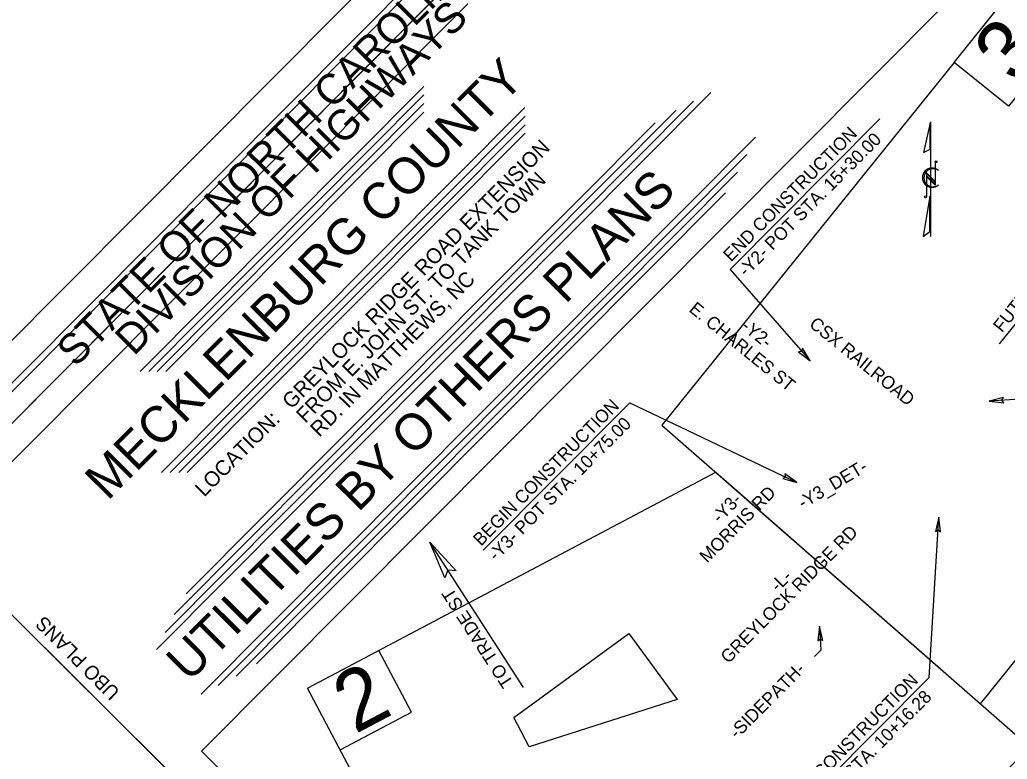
# Model space of a CAD drawing. Extents: x 1484850 to 1495577, y 495475 to 506245.
# Drawn here: x 1486494 to 1488945, y 498431 to 500266 of the extents above; entities that cross this region are included whole.
import ezdxf

# ---------------------------------------------------------------- set-up
doc = ezdxf.new("R2010")
doc.units = 0
for name, color, linetype in [('Cell Prop Down Guy _B', 7, 'Continuous'), ('Exist Conduit _B', 7, 'Continuous'), ('Exist Utilities Sanitary Sewer Manhole CELL', 7, 'Continuous'), ('Exist Utilities Telephone UG Cable SUE LOS C', 7, 'Continuous'), ('Exist Utilities Telephone UG FO SUE LOS C', 7, 'Continuous'), ('Exist Utilities Water Fire Hydrant CELL', 7, 'Continuous'), ('Exist Utilities Water Meter CELL', 7, 'Continuous'), ('Exist Utilities Water UG Line SUE LOS B', 7, 'Continuous'), ('Exist Utilities Water UG Line SUE LOS C', 7, 'Continuous'), ('Exist Utilities Water Valve CELL', 7, 'Continuous'), ('P Pole (Pow Co) CELL', 7, 'Continuous'), ('Prop Conduit _B', 7, 'Continuous'), ('Prop Guy Wire', 7, 'Continuous'), ('Prop OH Pow Lines', 7, 'Continuous'), ('Prop UG Pow Cables', 7, 'Continuous')]:
    doc.layers.add(name, color=color, linetype=linetype)

msp = doc.modelspace()

# ---------------------------------------------------------------- linework, layer by layer
at = {"layer": 'Cell Prop Down Guy _B'}
msp.add_line((1485019.4, 497803.9), (1488584.2, 501383.6), dxfattribs=at)
msp.add_lwpolyline([(1485019.4, 497803.9), (1488584.2, 501383.6), (1490922.5, 499055), (1487357.7, 495475.3)], close=True, dxfattribs=at)
at = {"layer": 'Exist Utilities Sanitary Sewer Manhole CELL'}
for points in [[(1488427.6, 499442.4), (1488455.9, 499419.4), (1488436.9, 499450.9), (1488435.1, 499443.2)], [(1488936.2, 499328.4), (1488900.6, 499320), (1488937.2, 499315.8), (1488932.2, 499321.9)], [(1488388, 499127.6), (1488423.2, 499117.7), (1488393.3, 499139.1), (1488394.7, 499131.3)], [(1488779.9, 498995.6), (1488775.9, 499031.9), (1488767.3, 498996.2), (1488773.9, 499000.4)], [(1487549.6, 498881.6), (1487511.9, 498969.7), (1487577.7, 498899.1), (1487557, 498900.1)], [(1488487.6, 498726.2), (1488479.7, 498761.9), (1488475.1, 498725.4), (1488481.2, 498730.3)]]:
    msp.add_lwpolyline(points, close=True, dxfattribs=at)
at = {"layer": 'Exist Utilities Telephone UG Cable SUE LOS C'}
for points in [[(1486945.7, 498451.8), (1488980.9, 500495.4), (1490008.1, 499472.4), (1487973, 497428.8)], [(1486945.7, 498451.8), (1488980.9, 500495.4), (1490008.1, 499472.4), (1487973, 497428.8)], [(1487759, 498462.3), (1487720.6, 498534.8), (1488006.4, 498743.3), (1488126.2, 498579.3)]]:
    msp.add_lwpolyline(points, close=True, dxfattribs=at)
at = {"layer": 'Exist Utilities Telephone UG FO SUE LOS C'}
for points in [[(1488813.3, 500160.1), (1488938.9, 500315.8), (1489073.9, 500206.9)], [(1487289.7, 498454.6), (1487466.6, 498548.1), (1487385.6, 498701.5)]]:
    msp.add_lwpolyline(points, dxfattribs=at)
for points in [[(1488948.4, 500051.2), (1488813.3, 500160.1), (1488087.8, 499260.5), (1488879.1, 498569.1), (1489756.2, 499656.7), (1489073.9, 500206.9)], [(1487208.7, 498608.1), (1488222.1, 499143.2), (1488965.4, 498493.7), (1489025.4, 498380), (1487698.9, 497679.6)]]:
    msp.add_lwpolyline(points, close=True, dxfattribs=at)
at = {"layer": 'Exist Utilities Water Fire Hydrant CELL'}
for p, q in [((1488755.5, 499728.3), (1488755.8, 500012.8)), ((1488766.4, 499913.8), (1488766.4, 499855.4)), ((1488766.4, 499864.5), (1488744.6, 499886.3)), ((1488744.6, 499886.3), (1488744.6, 499826.9)), ((1488766.4, 499862.4), (1488744.6, 499884.1)), ((1488744.6, 499884.1), (1488744.6, 499878.8)), ((1488766.4, 499857), (1488744.6, 499878.8)), ((1488744.6, 499878.8), (1488766.4, 499857)), ((1488766.4, 499855.4), (1488744.6, 499877.2)), ((1488774.4, 499892), (1488774.7, 499891.8)), ((1488766.4, 499857), (1488766.4, 499862.4))]:
    msp.add_line(p, q, dxfattribs=at)
for points in [[(1488753.8, 500010.3), (1488737.5, 499936.4), (1488753.7, 499944.6)], [(1488753.3, 499828.5), (1488737.1, 499728.3), (1488753.2, 499741)]]:
    msp.add_lwpolyline(points, close=True, dxfattribs=at)
for centre in [(1488768.7, 499913.7), (1488742.3, 499826.8)]:
    msp.add_circle(centre, 2.32, dxfattribs=at)
for centre, radius, start, end in [((1488758.7, 499874.1), 23.9, 47.7961, 312.3501), ((1488761, 499874.1), 22.4, 53.0511, 308.5848)]:
    msp.add_arc(centre, radius, start, end, dxfattribs=at)
at = {"layer": 'Exist Utilities Water Meter CELL'}
for p, q in [((1488926.4, 499461.8), (1489269, 499886.6)), ((1487745, 498609.8), (1487511.9, 498969.7))]:
    msp.add_line(p, q, dxfattribs=at)
at = {"layer": 'Exist Utilities Water UG Line SUE LOS B'}
for p, q in [((1488629.3, 500020.1), (1488257.4, 499646.7)), ((1488257.4, 499646.7), (1488455.9, 499419.4)), ((1489242.3, 499341.4), (1488900.6, 499320)), ((1488009, 499315.3), (1487644.9, 498949.7)), ((1488009, 499315.3), (1488423.2, 499117.7)), ((1488751.5, 498634.5), (1488775.9, 499031.9)), ((1488479.7, 498761.9), (1488482.6, 498702.3)), ((1488482.6, 498702.3), (1488466.7, 498686.4)), ((1488751.5, 498634.5), (1488387.4, 498268.8))]:
    msp.add_line(p, q, dxfattribs=at)
at = {"layer": 'Exist Utilities Water UG Line SUE LOS C'}
for points in [[(1486441.9, 498821.9), (1486895.2, 498370.5), (1486217.1, 497689.6), (1485587.2, 498316.9), (1486082.4, 498814.2), (1486259, 498638.3)], [(1486441.9, 498821.9), (1486895.4, 498370.4), (1486217.3, 497689.5), (1485587.4, 498316.8), (1486082.5, 498814.1), (1486259, 498638.3)]]:
    msp.add_lwpolyline(points, close=True, dxfattribs=at)
at = {"layer": 'P Pole (Pow Co) CELL'}
msp.add_lwpolyline([(1488481.3, 501486.1), (1484916.4, 497906.4), (1487254.7, 495577.9), (1490819.6, 499157.6)], close=True, dxfattribs=at)
at = {"layer": 'Prop Guy Wire'}
msp.add_lwpolyline([(1487337.5, 495550.5), (1490865.3, 499093), (1488622.4, 501326.5), (1485094.6, 497784)], close=True, dxfattribs=at)
at = {"layer": 'Prop OH Pow Lines'}
for p, q in [((1487638.7, 499770.2), (1487638.7, 499770.2)), ((1487269, 499630.1), (1487269, 499630.1))]:
    msp.add_line(p, q, dxfattribs=at)
at = {"layer": 'Prop UG Pow Cables'}
for p, q in [((1486793.1, 499393.2), (1487497.5, 500100.5)), ((1486814.3, 499393.3), (1487497.5, 500079.3)), ((1486833.6, 498703.5), (1488209.3, 500085.1)), ((1486835.5, 499393.3), (1487497.6, 500058.1)), ((1486846.5, 499142.5), (1487748.3, 500048)), ((1486854.9, 498746.2), (1488166.8, 500063.6)), ((1486856.7, 499393.3), (1487497.6, 500036.9)), ((1486867.7, 499142.5), (1487748.4, 500026.8)), ((1486877.7, 498790.4), (1488122.8, 500040.6)), ((1486889, 499142.5), (1487748.4, 500005.6)), ((1486907.7, 498841.7), (1488071.5, 500010.4)), ((1486910.2, 499142.6), (1487748.5, 499984.4)), ((1486944.4, 498593.2), (1488320.2, 499974.6)), ((1486987, 498614.6), (1488299, 499932)), ((1487031.1, 498637.6), (1488276.1, 499887.9)), ((1487082.3, 498667.9), (1488246.1, 499836.5))]:
    msp.add_line(p, q, dxfattribs=at)
for points in [[(1488477.3, 501375.9), (1485344.2, 498229.8)], [(1488477.3, 501354.6), (1485471.3, 498336.1)]]:
    msp.add_lwpolyline(points, dxfattribs=at)
for points in [[(1486895.2, 498370.5), (1486217.1, 497689.6), (1485587.2, 498316.9), (1486265.2, 498997.8)], [(1485587.2, 498316.9), (1486082.4, 498814.2), (1486259, 498638.3), (1486441.9, 498821.9), (1486895, 498370.6), (1486217, 497689.7)]]:
    msp.add_lwpolyline(points, close=True, dxfattribs=at)

# ---------------------------------------------------------------- texts
at = {"layer": 'Exist Conduit _B'}
for s, height, p in [('MECKLENBURG COUNTY', 90, (1486712.2, 499070.9)), ('GREYLOCK RIDGE ROAD EXTENSION', 37.5, (1487168.4, 499298.1)), ('UTILITIES BY OTHERS PLANS', 90, (1486914.2, 498620.5)), ('FROM E. JOHN ST. TO TANK TOWN ', 37.5, (1487203.3, 499263.4)), ('RD. IN MATTHEWS, NC', 37.5, (1487238.1, 499228.7))]:
    msp.add_text(s, height=height, rotation=45.1191, dxfattribs=at).set_placement(p)
at = {"layer": 'Exist Utilities Water Meter CELL'}
for s, height, rotation, p in [('3', 150, 51.1156, (1488968.4, 500102.7)), ('END CONSTRUCTION', 32, 45.1191, (1488259.9, 499663.9)), ('-Y2- POT STA. 15+30.00', 32, 45.1191, (1488297.3, 499626.7)), ('FUTURE EXTENSION', 32, 51.1158, (1488932.5, 499488.1)), ('BEGIN CONSTRUCTION', 32, 45.1191, (1487638.9, 498958.4)), ('-Y3- POT STA. 10+75.00', 32, 45.1191, (1487676.3, 498921.1)), ('TO TRADE ST', 32, 122.9223, (1487720.8, 498621.8)), ('2', 150, 27.8403, (1487326.4, 498493)), ('BEGIN CONSTRUCTION', 32, 45.1191, (1488381.4, 498277.5)), ('-Y2- POC STA. 10+16.28', 32, 45.1191, (1488418.8, 498240.3))]:
    msp.add_text(s, height=height, rotation=rotation, dxfattribs=at).set_placement(p)
at = {"layer": 'Exist Utilities Water Valve CELL'}
for s, rotation, p in [('E. CHARLES ST', 320.9673, (1488153.4, 499543.8)), ('-Y2-', 320.9673, (1488283.1, 499500.5)), ('CSX RAILROAD', 320.9673, (1488451.5, 499506.6)), ('-Y3_DET-', 30.8554, (1488438.1, 499051.3)), ('MORRIS RD', 45.1191, (1488200.7, 498916.5)), ('-Y3-', 45.1191, (1488231.3, 499015.3)), ('GREYLOCK RIDGE RD', 45.1191, (1488253.2, 498667)), ('-L-', 45.1191, (1488376.4, 498845)), ('-SIDEPATH-', 45.1191, (1488274.8, 498480.3))]:
    msp.add_text(s, height=32, rotation=rotation, dxfattribs=at).set_placement(p)
at = {"layer": 'Prop Conduit _B'}
msp.add_text('UBO PLANS', height=35.01, rotation=135.1191, dxfattribs=at).set_placement((1486744.7, 498599.8))
at = {"layer": 'Prop UG Pow Cables'}
for s, height, p in [('STATE OF NORTH CAROLINA', 75, (1486632.4, 499401.7)), ('DIVISION OF HIGHWAYS', 75, (1486777.4, 499430.4)), ('LOCATION: ', 37.5, (1486952, 499080.6))]:
    msp.add_text(s, height=height, rotation=45.1191, dxfattribs=at).set_placement(p)

doc.saveas('drawing.dxf')
